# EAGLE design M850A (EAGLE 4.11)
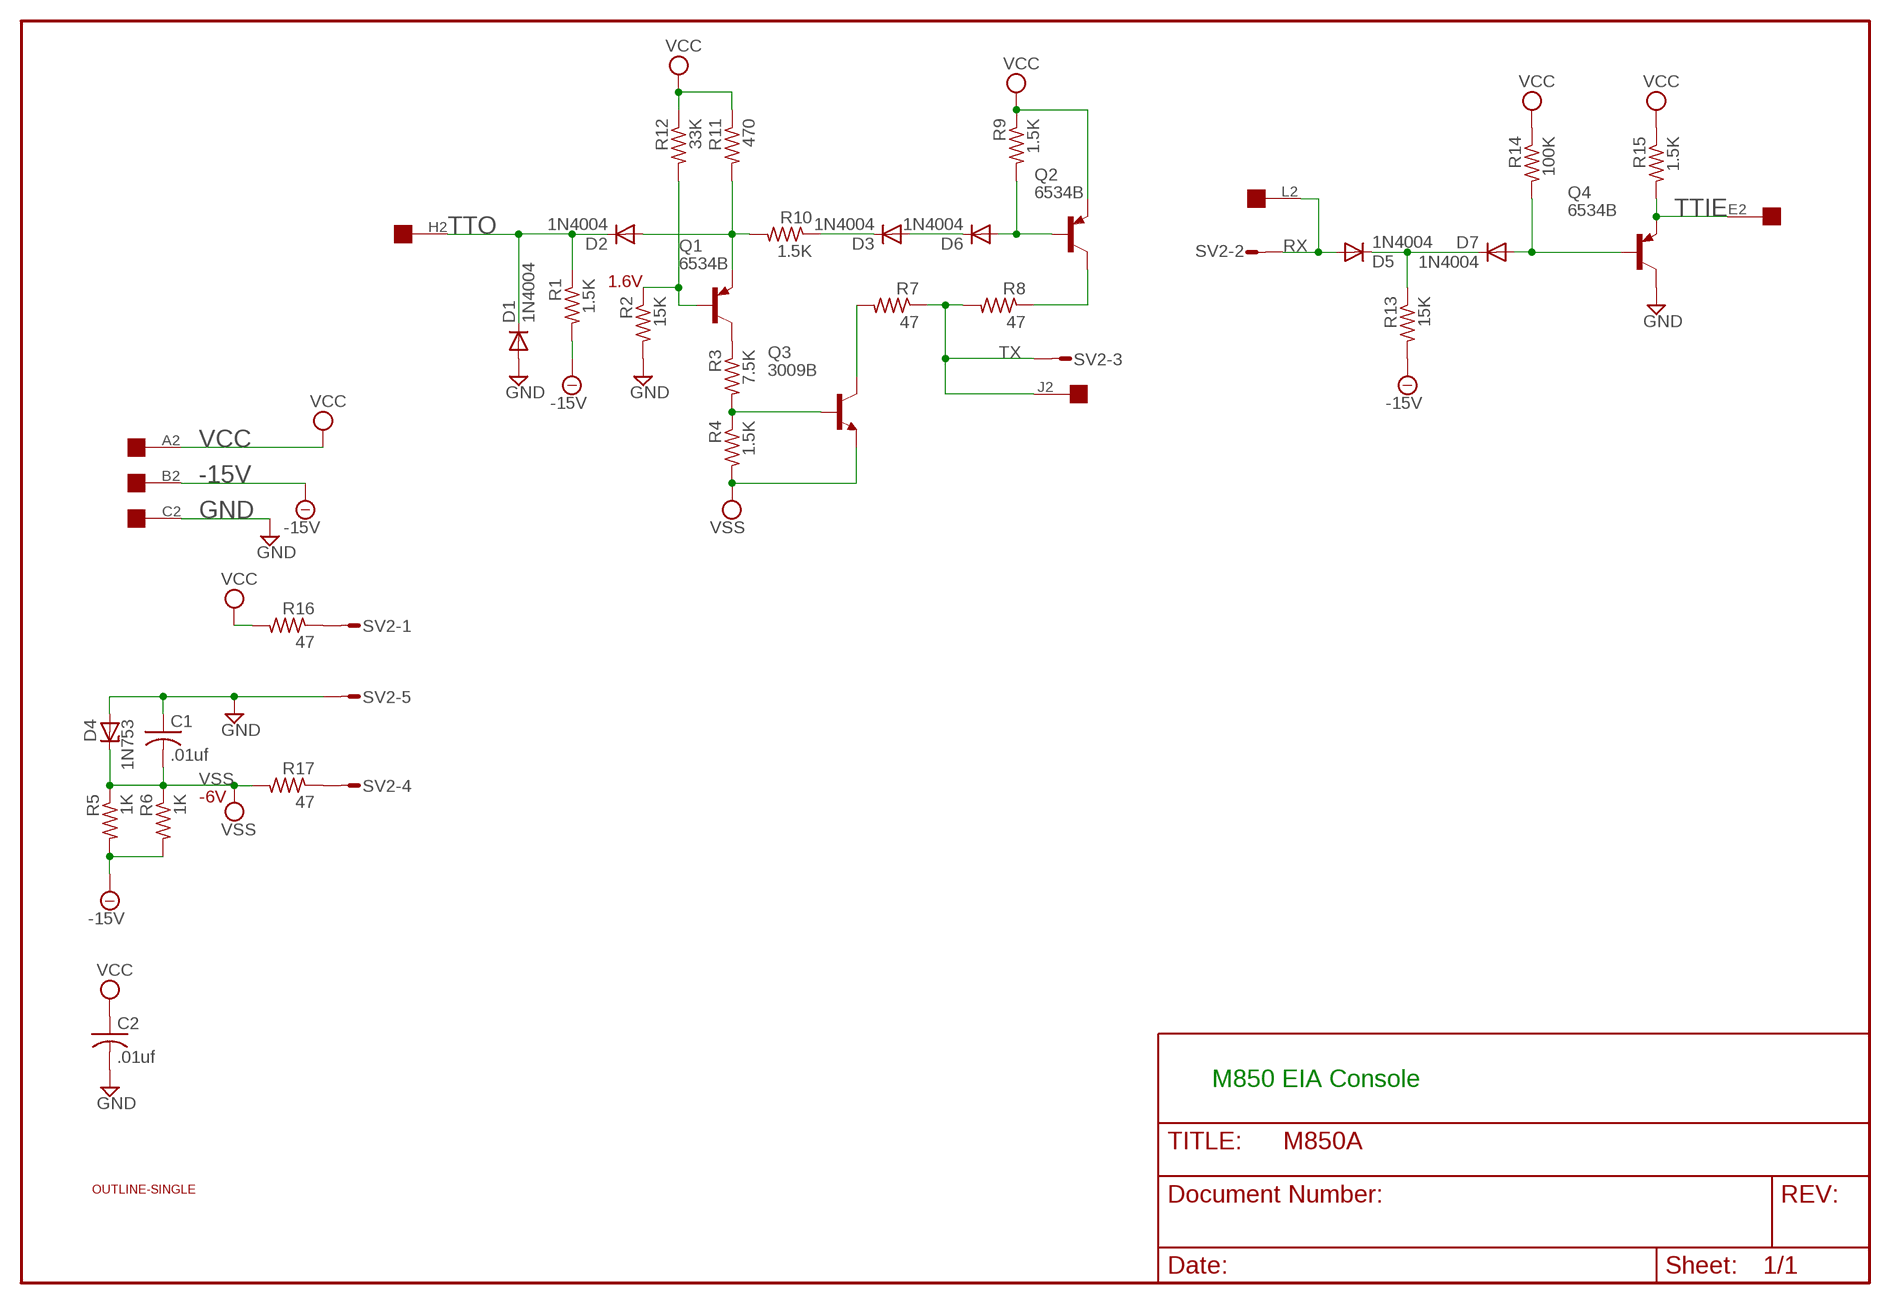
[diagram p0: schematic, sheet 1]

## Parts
C1  .01uf  C-US050-025X075  [C050-025X075]
C2  .01uf  C-US050-025X075  [C050-025X075]
D1  1N4004  1N4148  [DO35-10]
D2  1N4004  1N4148  [DO35-10]
D3  1N4004  1N4148  [DO35-10]
D4  1N753  ZENER-DIODEDO35Z10  [DO35Z10]
D5  1N4004  1N4148  [DO35-10]
D6  1N4004  1N4148  [DO35-10]
D7  1N4004  1N4148  [DO35-10]
EDGE  EDGE-1  [EDGE-CON1]
Q1  6534B  -PNP-TO92/  [TO92/]
Q2  6534B  -PNP-TO92/  [TO92/]
Q3  3009B  -NPN-TO18-  [TO18-]
Q4  6534B  -PNP-TO92/  [TO92/]
R1  1.5K  R-US_0207/10  [0207/10]
R2  15K  R-US_0207/10  [0207/10]
R3  7.5K  R-US_0207/10  [0207/10]
R4  1.5K  R-US_0207/10  [0207/10]
R5  1K  R-US_0207/10  [0207/10]
R6  1K  R-US_0207/10  [0207/10]
R7  47  R-US_0207/10  [0207/10]
R8  47  R-US_0207/10  [0207/10]
R9  1.5K  R-US_0207/10  [0207/10]
R10  1.5K  R-US_0207/10  [0207/10]
R11  470  R-US_0207/10  [0207/10]
R12  33K  R-US_0207/10  [0207/10]
R13  15K  R-US_0207/10  [0207/10]
R14  100K  R-US_0207/10  [0207/10]
R15  1.5K  R-US_0207/10  [0207/10]
R16  47  R-US_0207/10  [0207/10]
R17  47  R-US_0207/10  [0207/10]
SV2  L08P  [L08P]
U$1  OUTLINE-SINGLE  [SINGLE]

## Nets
-15V: EDGE.B2 R1.2 R5.2 R6.2 R13.2
GND: C1.1 C2.2 D1.A D4.A EDGE.C2 Q4.3(C) R2.2 SV2.5
N$1: Q2.3(C) R8.1
N$2: D7.A Q4.2(B) R14.2
N$4: Q1.3(C) R3.1
N$7: R17.1 SV2.4
N$8: Q3.3(C) R7.2
N$9: D5.C D7.C R13.1
N$10: D2.A Q1.1(E) R10.2 R11.2
N$11: D6.A Q2.2(B) R9.2
N$12: Q1.2(B) R2.1 R12.2
N$13: D3.A D6.C
N$14: D3.C R10.1
N$15: Q3.2(B) R3.2 R4.1
N$16: R16.1 SV2.1
RX: D5.A EDGE.L2 SV2.2
TTIE: EDGE.E2 Q4.1(E) R15.2
TTO: D1.C D2.C EDGE.H2 R1.1
TX: EDGE.J2 R7.1 R8.2 SV2.3
VCC: C2.1 EDGE.A2 Q2.1(E) R9.1 R11.1 R12.1 R14.1 R15.1 R16.2
VSS: C1.2 D4.C Q3.1(E) R4.2 R5.1 R6.1 R17.2
Unconnected: EDGE.D2 EDGE.F2 EDGE.K2 EDGE.M2 EDGE.N2 EDGE.P2 EDGE.R2 EDGE.S2 EDGE.T2 EDGE.U2 EDGE.V2 SV2.6 SV2.7 SV2.8

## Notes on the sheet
- 1.6V
- -6V
- M850 EIA Console

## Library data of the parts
C1 C2 = rcl:C-US: CAPACITOR, American symbol
D1-D3 D5-D7 = diode:1N4148: DIODE
D4 = diode:ZENER-DIODE: Z-Diode
EDGE = dec-con:EDGE-1: Single-Sided DEC Edge Connector -- (side 2)
Q1 Q2 Q4 = transistor:*-PNP-: PNP Transistror
Q3 = transistor:*-NPN-: NPN Transistror
R1-R17 = rcl:R-US_: RESISTOR, American symbol
SV2 = con-amp-mt:L08P: AMP MT CONNECTOR
U$1 = dec-con:OUTLINE-*: Board outlines for DEC boards.

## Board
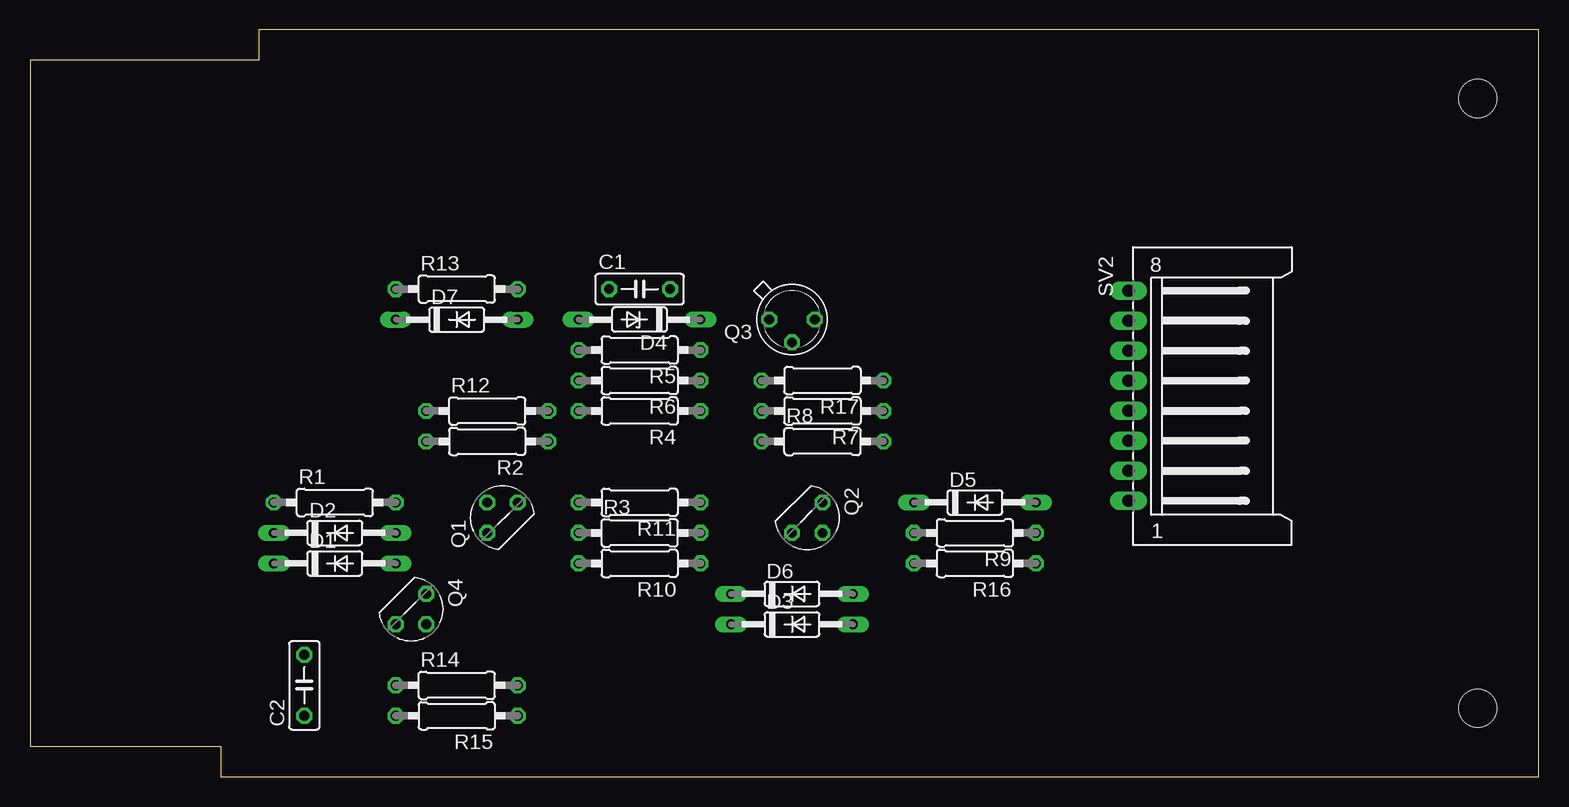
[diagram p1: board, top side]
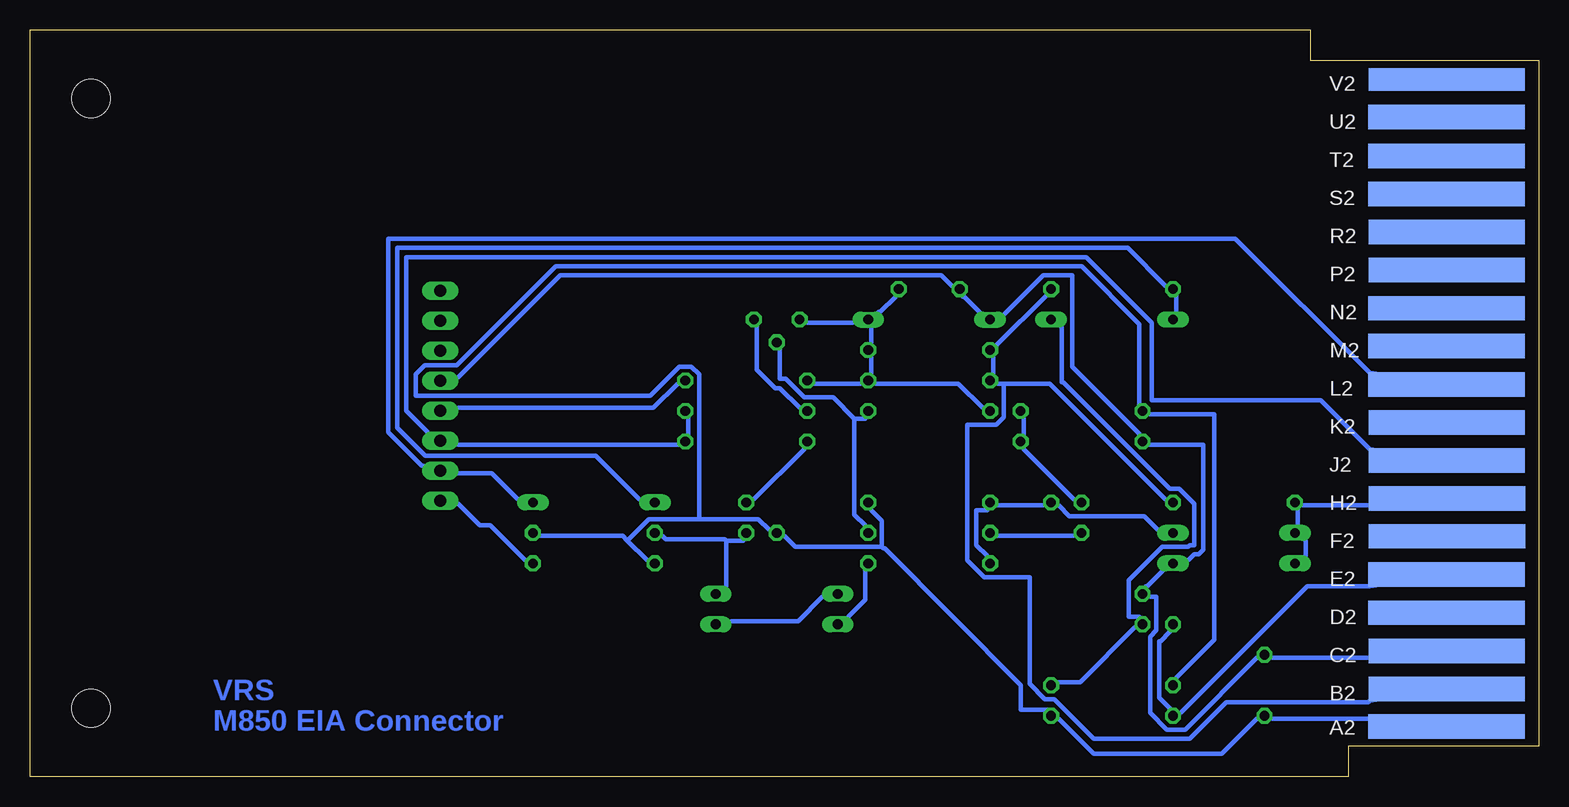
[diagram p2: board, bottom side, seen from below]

Size 125.73 x 62.23 mm. Coordinates in mm from the lower left corner, seen from the top.
Copper layers (1*16): Top 0.035mm / dielectric 1.5mm / Bottom 0.035mm
Design rules "15mils": minimum track width 15mil, minimum drill 24mil, track to track 15mil, track to pad 10mil, pad to pad 10mil, via to via 10mil, smd to smd 10mil, copper to edge 25mil, drill to drill 10mil, minimum pad ring 10mil, minimum via ring 8mil, stop-mask expansion 0mil, vias tented up to drill 0mil, thermal gap 10mil

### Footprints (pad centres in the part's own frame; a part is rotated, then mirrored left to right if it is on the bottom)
C050-025X075 = drill 0.813 octagon: 1 -2.54,0; 2 2.54,0
DO35-10 = drill 0.813 long: A 5.08,0; C -5.08,0
DO35Z10 = drill 0.813 long: A 5.08,0; C -5.08,0
EDGE-CON1 = smd 13.017 x 2.032 bottom: A2 7.69,4.194; B2 7.668,7.328; C2 7.668,10.49; D2 7.693,13.665; E2 7.693,16.84; F2 7.642,20.041; H2 7.642,23.19; J2 7.668,26.34; K2 7.668,29.515; L2 7.693,32.69; M2 7.693,35.89; N2 7.693,39.04; P2 7.668,42.24; R2 7.668,45.39; S2 7.693,48.565; T2 7.693,51.74; U2 7.693,54.966 | smd 13.017 x 1.905 bottom: V2 7.668,58.102
TO92/ = drill 0.813 octagon: 1 1.27,-1.27; 2 1.27,1.27; 3 -1.27,1.27
TO18- = drill 0.813 octagon: 1 1.905,0; 2 0,1.905; 3 -1.905,0
0207/10 = drill 0.813 octagon: 1 -5.08,0; 2 5.08,0
L08P = drill 1.016 long: 1 8.75,-6.25; 2 6.25,-6.25; 3 3.75,-6.25; 4 1.25,-6.25; 5 -1.25,-6.25; 6 -3.75,-6.25; 7 -6.25,-6.25; 8 -8.75,-6.25
SINGLE = hole 3.175: 120.65,56.515; 120.65,5.715

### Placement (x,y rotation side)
C1  50.8,40.64 0 top
C2  22.86,7.62 90 top
D1  25.4,17.78 0 top
D2  25.4,20.32 0 top
D3  63.5,12.7 0 top
D4  50.8,38.1 180 top
D5  78.74,22.86 0 top
D6  63.5,15.24 0 top
D7  35.56,38.1 0 top
EDGE  0,0 0 top
Q1  39.37,21.59 90 top
Q2  64.77,21.59 270 top
Q3  63.5,38.1 180 top
Q4  31.75,13.97 270 top
R1  25.4,22.86 0 top
R2  38.1,27.94 180 top
R3  50.8,20.32 0 top
R4  50.8,30.48 180 top
R5  50.8,35.56 180 top
R6  50.8,33.02 180 top
R7  66.04,30.48 180 top
R8  66.04,27.94 0 top
R9  78.74,20.32 180 top
R10  50.8,17.78 180 top
R11  50.8,22.86 180 top
R12  38.1,30.48 0 top
R13  35.56,40.64 0 top
R14  35.56,7.62 0 top
R15  35.56,5.08 180 top
R16  78.74,17.78 180 top
R17  66.04,33.02 180 top
SV2  97.79,31.75 270 top
U$1  0,0 0 top

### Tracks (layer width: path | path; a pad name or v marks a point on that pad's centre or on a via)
-15V
  Bottom 0.381: 44.58,32.77 40.77,32.77 31.12,23.11 R1.2 | 44.58,32.77 45.09,32.77 R6.2 45.47,33.66 45.47,34.92 R5.2 45.21,35.94 41.02,40.13 R13.2 | EDGE.B2 14.1,6.35 14.22,6.22 26.04,6.22 29.08,3.17 37.08,3.17 40.39,6.48 41.15,6.48 42.42,7.75 42.42,16.64 46.23,16.64 47.63,18.03 47.63,29.34 45.21,29.34 44.58,29.97 44.58,32.77
GND
  Bottom 0.381: EDGE.C2 14.1,9.91 22.23,9.91 C2.2 23.5,9.91 29.46,3.94 30.99,3.94 32.39,5.33 32.39,11.68 31.88,12.19 31.88,14.99 32.39,14.99 Q4.3 32.77,15.88 32.64,15.88 31.37,17.14 D1.A 29.21,18.03 28.7,18.54 28.32,18.54 27.94,18.92 27.94,27.69 32.39,27.69 R2.2 33.27,28.57 38.86,34.16 38.86,41.78 41.28,41.78 44.58,38.48 D4.A 46.61,38.73 47.88,40.01 48.01,40.01 C1.1 48.9,40.89 49.78,41.78 81.53,41.78 90.04,33.27 SV2.5
N$1
  Bottom 0.381: R8.1 61.21,27.3 65.41,23.11 Q2.3
N$2
  Bottom 0.381: R14.2 40.01,7.87 38.23,7.87 33.66,12.45 Q4.2 33.27,13.34 34.16,13.34 34.16,16.38 31.37,19.18 29.21,19.18 29.08,19.3 28.7,19.3 28.7,22.73 29.97,24 30.73,24 39.62,32.89 39.75,32.89 39.75,37.47 D7.A
N$4
  Bottom 0.381: Q1.3 38.74,20.07 45.09,20.07 R3.1
N$7
  Bottom 0.381: R17.1 71.76,32.77 73.79,30.73 90.04,30.73 SV2.4
N$8
  Bottom 0.381: R7.2 61.6,30.73 63.25,32.38 63.63,32.38 65.15,33.91 65.15,37.47 Q3.3
N$9
  Bottom 0.381: D7.C 30.23,38.73 30.23,40.01 R13.1 31.12,40.92 34.27,44.07 95.12,44.07 95.12,29.08 92.81,26.77 78.59,26.77 74.96,23.14 D5.C
N$10
  Bottom 0.381: R10.2 45.97,18.41 46.86,19.3 46.86,22.23 45.97,22.23 R11.2 45.09,22.61 41.28,22.61 Q1.1 40.01,22.61 39.12,21.72 32.89,21.72 31.75,20.57 D2.A
N$11
  Bottom 0.381: 67.69,19.68 67.69,15.88 D6.A | 67.69,19.68 66.29,19.68 Q2.2 | R9.2 73.03,20.07 72.77,19.81 67.82,19.81 67.69,19.68
N$12
  Bottom 0.381: Q1.2 38.74,23.11 42.93,27.3 R2.1 42.93,28.57 42.93,29.84 R12.2
N$13
  Bottom 0.381: D6.C 59.69,14.99 61.72,12.95 67.31,12.95 D3.A
N$14
  Bottom 0.381: D3.C 57.53,13.34 56.13,14.73 56.13,17.14 R10.1
N$15
  Bottom 0.381: 57.02,29.84 57.02,21.84 56.13,20.95 R3.2 | 57.02,29.84 56.13,29.84 R4.1 | Q3.2 63.25,35.56 63.25,33.15 62.74,33.15 61.21,31.62 58.8,31.62 57.02,29.84
N$16
  Bottom 0.381: R16.1 84.46,18.03 87.38,20.95 88.27,20.95 90.04,22.73 SV2.1
RX
  Bottom 0.381: D5.A 85.09,23.11 87.25,25.27 90.04,25.27 SV2.2 92.96,25.91 93.09,25.91 95.89,28.7 95.89,44.83 25.27,44.83 14.1,33.66 EDGE.L2
TTIE
  Bottom 0.381: Q4.1 30.73,12.06 31.5,11.3 31.62,11.3 31.62,6.6 30.73,5.71 R15.2 29.85,5.33 19.3,15.88 14.1,15.88 EDGE.E2
TTO
  Bottom 0.381: D1.C 19.43,18.41 19.43,19.68 D2.C 20.07,20.95 20.07,22.23 R1.1 19.69,22.61 14.1,22.61 EDGE.H2
TX
  Bottom 0.381: R7.1 70.87,29.84 70.87,28.57 R8.2 71.76,27.69 90.04,27.69 SV2.3 92.58,28.7 94.36,30.48 94.36,43.31 37.72,43.31 32.26,37.85 32.26,31.37 18.16,31.37 14.1,27.3 EDGE.J2
VCC
  Bottom 0.381: EDGE.A2 14.1,4.83 22.23,4.83 C2.1 23.5,4.83 26.42,1.91 37.08,1.91 40.01,4.83 R15.1 41.02,5.59 43.18,5.59 43.18,7.62 54.48,19.05 54.61,19.05 54.74,19.18 | R14.1 30.23,8.26 27.05,11.43 27.05,30.23 32.39,30.23 R12.1 33.27,31.11 33.27,37.72 38.1,42.55 81.92,42.55 90.17,34.29 92.84,34.29 93.6,33.53 93.6,31.75 74.04,31.75 71.63,34.16 70.61,34.16 69.98,33.53 69.98,21.46 | 54.74,19.18 54.74,21.34 55.63,22.23 R11.1 | 54.74,19.18 61.98,19.18 62.87,20.07 Q2.1 64.14,20.57 65.02,21.46 69.98,21.46 | 75.95,19.68 76.33,20.07 83.19,20.07 R9.1 | 75.95,19.68 74.3,18.03 R16.2 | 69.98,21.46 74.17,21.46 75.95,19.68
VSS
  Bottom 0.381: R4.2 46.36,30.73 48.39,32.77 55.25,32.77 R6.1 | R6.1 55.63,33.66 55.63,34.92 R5.1 55.63,36.2 55.63,37.47 D4.C | R17.2 60.33,32.77 56.52,32.77 R6.1 | Q3.1 60.96,37.85 57.15,37.85 D4.C | C1.2 53.59,40.01 54.86,38.73 54.99,38.73 D4.C

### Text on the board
Bottom: VRS | M850 EIA Connector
